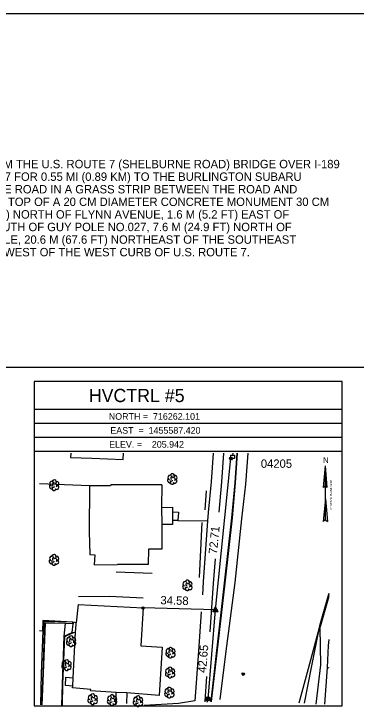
# Model space of a CAD drawing. Extents: x 1454512 to 1455152, y 715836 to 716256.
# Drawn here: x 1454659.9 to 1454782.2, y 716007.5 to 716255.5 of the extents above; entities that cross this region are included whole.
import ezdxf

# ---------------------------------------------------------------- set-up
doc = ezdxf.new("R2010")
doc.units = 0
for name, color, linetype in [('CBP', 7, 'Continuous'), ('CPSM', 7, 'Continuous'), ('Default', 7, 'Continuous'), ('LAHR', 7, 'Continuous'), ('LAPB', 7, 'Continuous'), ('LBC', 7, 'Continuous'), ('LBF', 7, 'Continuous'), ('LFNC', 7, 'Continuous'), ('LSH', 7, 'Continuous'), ('LTD', 7, 'Continuous'), ('LW', 7, 'Continuous'), ('NBL1', 7, 'Continuous'), ('NBL2', 7, 'Continuous'), ('NNA_P', 7, 'Continuous'), ('PET', 7, 'Continuous'), ('PSP', 7, 'Continuous'), ('RC', 7, 'Continuous'), ('RDG', 7, 'Continuous'), ('RDP', 7, 'Continuous'), ('RSW', 7, 'Continuous'), ('U_C', 7, 'Continuous'), ('UEPT', 7, 'Continuous'), ('UGV', 7, 'Continuous')]:
    doc.layers.add(name, color=color, linetype=linetype)

msp = doc.modelspace()

# ---------------------------------------------------------------- linework, layer by layer
at = {"layer": 'CBP'}
for centre, radius in [((1454737.38, 716096.54), 0.469), ((1454737.38, 716096.54), 0.0625), ((1454706, 716043), 0.469), ((1454706, 716043), 0.0625), ((1454729.24, 716010.41), 0.469), ((1454729.24, 716010.41), 0.0625)]:
    msp.add_circle(centre, radius, dxfattribs=at)
at = {"layer": 'CPSM'}
for p, q in [((1454730.98, 716041.74), (1454731.92, 716043.37)), ((1454730.98, 716041.74), (1454731.92, 716042.29)), ((1454730.98, 716041.74), (1454732.86, 716041.74)), ((1454732.86, 716041.74), (1454731.92, 716043.37)), ((1454731.92, 716042.29), (1454731.92, 716043.37)), ((1454731.92, 716042.29), (1454731.92, 716042.29)), ((1454731.92, 716042.29), (1454732.86, 716041.74))]:
    msp.add_line(p, q, dxfattribs=at)
at = {"layer": 'Default'}
for p, q in [((1454731.92, 716042.29), (1454737.38, 716096.54)), ((1454731.92, 716042.29), (1454706, 716043)), ((1454729.24, 716010.41), (1454731.92, 716042.29))]:
    msp.add_line(p, q, dxfattribs=at)
at = {"layer": 'LAHR'}
for points in [[(1454728.58, 716084.91), (1454728.12, 716078.17)], [(1454727.03, 716073.56), (1454726.06, 716053.94)], [(1454709.26, 716055.34), (1454696.46, 716055.8)], [(1454682.91, 716047.17), (1454694.02, 716047.24), (1454706.11, 716046.67)]]:
    msp.add_lwpolyline(points, dxfattribs=at)
at = {"layer": 'LAPB'}
msp.add_lwpolyline([(1454680.96, 716037.97), (1454670.18, 716038.49), (1454670.14, 716034.69), (1454668.99, 716034.8)], dxfattribs=at)
at = {"layer": 'LBC'}
for points in [[(1454712.74, 716087.08), (1454704.74, 716087.07), (1454700.29, 716087.1), (1454694.46, 716087.11), (1454694.35, 716086.71), (1454690.28, 716086.68), (1454686.87, 716086.68), (1454686.73, 716070.41)], [(1454712.74, 716087.08), (1454712.63, 716078.92), (1454712.76, 716072.87), (1454712.7, 716064.08), (1454707.95, 716064.07), (1454707.9, 716058.5), (1454696.94, 716058.58)], [(1454682.85, 716044.21), (1454682.17, 716037.74)], [(1454682.85, 716044.21), (1454706.06, 716043.06), (1454705.24, 716029.42), (1454712.91, 716028.95), (1454711.78, 716011.74), (1454700.28, 716012.6), (1454696.46, 716012.83), (1454687.24, 716013.4), (1454687.42, 716013.81)], [(1454682.15, 716037.12), (1454682.17, 716037.74)]]:
    msp.add_lwpolyline(points, dxfattribs=at)
at = {"layer": 'LBF'}
for points in [[(1454680.22, 716098.33), (1454680.15, 716096.81), (1454687.68, 716096.64), (1454698.86, 716096.14), (1454699.04, 716098.33)], [(1454712.63, 716078.92), (1454716.49, 716079.01), (1454716.51, 716077.43), (1454716.6, 716074.26), (1454716.56, 716072.89), (1454712.76, 716072.87)], [(1454716.51, 716077.43), (1454718.64, 716077.3), (1454718.49, 716074.31), (1454716.6, 716074.26)], [(1454686.73, 716070.41), (1454687.01, 716062.12), (1454688.83, 716061.98), (1454688.61, 716058.49), (1454696.94, 716058.58)], [(1454687.42, 716013.81), (1454680.82, 716014.4), (1454680.87, 716015.04), (1454681.04, 716018.05), (1454681.93, 716034.34), (1454682.15, 716037.12)], [(1454682.17, 716037.74), (1454680.96, 716037.97), (1454681.01, 716037.28)], [(1454680.73, 716034.26), (1454681.93, 716034.34)], [(1454680.87, 716015.04), (1454678.29, 716015.23), (1454678.48, 716018.24), (1454681.04, 716018.05)], [(1454696.32, 716008.65), (1454696.46, 716012.83)], [(1454700.28, 716012.6), (1454700.12, 716008.79)]]:
    msp.add_lwpolyline(points, dxfattribs=at)
at = {"layer": 'LFNC'}
msp.add_lwpolyline([(1454686.87, 716086.68), (1454668.99, 716087.43)], dxfattribs=at)
at = {"layer": 'LSH'}
for p, q in [((1454680.28, 716031.14), (1454680.28, 716031.14)), ((1454680.28, 716031.14), (1454680.28, 716031.14)), ((1454715.8, 716027.07), (1454715.8, 716027.07)), ((1454715.8, 716027.07), (1454715.8, 716027.07)), ((1454678.68, 716022.59), (1454678.68, 716022.59)), ((1454678.68, 716022.59), (1454678.68, 716022.59)), ((1454715.66, 716019.94), (1454715.66, 716019.94)), ((1454715.66, 716019.94), (1454715.66, 716019.94)), ((1454715.41, 716012.76), (1454715.41, 716012.76)), ((1454715.41, 716012.76), (1454715.41, 716012.76)), ((1454694.92, 716010.11), (1454694.92, 716010.11)), ((1454694.92, 716010.11), (1454694.92, 716010.11)), ((1454704.2, 716009.69), (1454704.2, 716009.69)), ((1454704.2, 716009.69), (1454704.2, 716009.69))]:
    msp.add_line(p, q, dxfattribs=at)
for centre in [(1454680.32, 716032.22), (1454715.84, 716028.14), (1454678.71, 716023.67), (1454715.69, 716021.02), (1454715.44, 716013.84), (1454694.95, 716011.18), (1454704.23, 716010.77)]:
    msp.add_arc(centre, 0.785, 335.5272, 180.9563, dxfattribs=at)
for centre, major_axis, ratio, start_param, end_param in [((1454679.69, 716031.64), (0.908, -0.384), 0.895232, 1.570796, 4.712389), ((1454680.12, 716031.49), (-0.156, -0.594), 0.645439, 3.141593, 6.283185), ((1454680.66, 716031.02), (-0.375, 0.5), 0.989748, 3.141593, 6.283185), ((1454681.06, 716031.58), (-0.855, -0.362), 0.949671, 1.570796, 4.712389), ((1454679.47, 716030.61), (0.438, -0.781), 0.959034, 3.141593, 6.283185), ((1454680.28, 716030.02), (0.199, 0.796), 0.942809, 1.570796, 4.712389), ((1454679.94, 716030.58), (-0.469, -0.063), 0.423636, 0, 3.141593), ((1454681.03, 716030.52), (-0.817, 0.594), 0.841452, 1.570796, 4.712389), ((1454714.99, 716026.54), (0.438, -0.781), 0.959034, 3.141593, 6.283185), ((1454715.21, 716027.57), (0.908, -0.384), 0.895232, 1.570796, 4.712389), ((1454715.65, 716027.41), (-0.156, -0.594), 0.645439, 3.141593, 6.283185), ((1454716.18, 716026.94), (-0.375, 0.5), 0.989748, 3.141593, 6.283185), ((1454716.55, 716026.44), (-0.817, 0.594), 0.841452, 1.570796, 4.712389), ((1454716.58, 716027.5), (-0.855, -0.362), 0.949671, 1.570796, 4.712389), ((1454715.8, 716025.94), (0.199, 0.796), 0.942809, 1.570796, 4.712389), ((1454715.46, 716026.5), (-0.469, -0.063), 0.423636, 0, 3.141593), ((1454677.86, 716022.06), (0.438, -0.781), 0.959034, 3.141593, 6.283185), ((1454678.08, 716023.09), (0.908, -0.384), 0.895232, 1.570796, 4.712389), ((1454678.33, 716022.03), (-0.469, -0.063), 0.423636, 0, 3.141593), ((1454678.52, 716022.94), (-0.156, -0.594), 0.645439, 3.141593, 6.283185), ((1454679.05, 716022.47), (-0.375, 0.5), 0.989748, 3.141593, 6.283185), ((1454679.43, 716021.97), (-0.817, 0.594), 0.841452, 1.570796, 4.712389), ((1454679.46, 716023.03), (-0.855, -0.362), 0.949671, 1.570796, 4.712389), ((1454678.68, 716021.47), (0.199, 0.796), 0.942809, 1.570796, 4.712389), ((1454714.85, 716019.41), (0.438, -0.781), 0.959034, 3.141593, 6.283185), ((1454715.06, 716020.44), (0.908, -0.384), 0.895232, 1.570796, 4.712389), ((1454715.32, 716019.38), (-0.469, -0.063), 0.423636, 0, 3.141593), ((1454715.5, 716020.29), (-0.156, -0.594), 0.645439, 3.141593, 6.283185), ((1454716.03, 716019.82), (-0.375, 0.5), 0.989748, 3.141593, 6.283185), ((1454716.41, 716019.32), (-0.817, 0.594), 0.841452, 1.570796, 4.712389), ((1454716.44, 716020.38), (-0.855, -0.362), 0.949671, 1.570796, 4.712389), ((1454715.66, 716018.82), (0.199, 0.796), 0.942809, 1.570796, 4.712389), ((1454714.81, 716013.26), (0.908, -0.384), 0.895232, 1.570796, 4.712389), ((1454714.6, 716012.23), (0.438, -0.781), 0.959034, 3.141593, 6.283185), ((1454715.41, 716011.63), (0.199, 0.796), 0.942809, 1.570796, 4.712389), ((1454715.06, 716012.2), (-0.469, -0.063), 0.423636, 0, 3.141593), ((1454715.25, 716013.1), (-0.156, -0.594), 0.645439, 3.141593, 6.283185), ((1454715.78, 716012.63), (-0.375, 0.5), 0.989748, 3.141593, 6.283185), ((1454716.16, 716012.13), (-0.817, 0.594), 0.841452, 1.570796, 4.712389), ((1454716.19, 716013.2), (-0.855, -0.362), 0.949671, 1.570796, 4.712389), ((1454694.1, 716009.57), (0.438, -0.781), 0.959034, 3.141593, 6.283185), ((1454694.32, 716010.61), (0.908, -0.384), 0.895232, 1.570796, 4.712389), ((1454694.57, 716009.54), (-0.469, -0.063), 0.423636, 0, 3.141593), ((1454694.76, 716010.45), (-0.156, -0.594), 0.645439, 3.141593, 6.283185), ((1454695.29, 716009.98), (-0.375, 0.5), 0.989748, 3.141593, 6.283185), ((1454695.67, 716009.48), (-0.817, 0.594), 0.841452, 1.570796, 4.712389), ((1454695.7, 716010.54), (-0.855, -0.362), 0.949671, 1.570796, 4.712389), ((1454703.38, 716009.16), (0.438, -0.781), 0.959034, 3.141593, 6.283185), ((1454703.6, 716010.19), (0.908, -0.384), 0.895232, 1.570796, 4.712389), ((1454704.04, 716010.04), (-0.156, -0.594), 0.645439, 3.141593, 6.283185), ((1454704.57, 716009.57), (-0.375, 0.5), 0.989748, 3.141593, 6.283185), ((1454704.95, 716009.07), (-0.817, 0.594), 0.841452, 1.570796, 4.712389), ((1454704.98, 716010.13), (-0.855, -0.362), 0.949671, 1.570796, 4.712389), ((1454694.92, 716008.98), (0.199, 0.796), 0.942809, 1.570796, 4.712389), ((1454704.2, 716008.57), (0.199, 0.796), 0.942809, 1.570796, 4.712389), ((1454703.85, 716009.13), (-0.469, -0.063), 0.423636, 0, 3.141593)]:
    msp.add_ellipse(centre, major_axis=major_axis, ratio=ratio, start_param=start_param, end_param=end_param, dxfattribs=at)
at = {"layer": 'LTD'}
for p, q in [((1454716.46, 716089.17), (1454716.46, 716089.17)), ((1454716.46, 716089.17), (1454716.46, 716089.17)), ((1454674.24, 716086.97), (1454674.24, 716086.97)), ((1454674.24, 716086.97), (1454674.24, 716086.97)), ((1454674.18, 716060.23), (1454674.18, 716060.23)), ((1454674.18, 716060.23), (1454674.18, 716060.23)), ((1454721.83, 716051.12), (1454721.83, 716051.12)), ((1454721.83, 716051.12), (1454721.83, 716051.12)), ((1454688, 716010.42), (1454688, 716010.42)), ((1454688, 716010.42), (1454688, 716010.42))]:
    msp.add_line(p, q, dxfattribs=at)
for centre in [(1454674.28, 716088.04), (1454716.5, 716090.25), (1454674.22, 716061.31), (1454721.86, 716052.2), (1454688.03, 716011.5)]:
    msp.add_arc(centre, 0.785, 335.5272, 180.9563, dxfattribs=at)
for centre, major_axis, ratio, start_param, end_param in [((1454715.65, 716088.64), (0.438, -0.781), 0.959034, 3.141593, 6.283185), ((1454715.87, 716089.67), (0.908, -0.384), 0.895232, 1.570796, 4.712389), ((1454716.12, 716088.61), (-0.469, -0.063), 0.423636, 0, 3.141593), ((1454716.3, 716089.52), (-0.156, -0.594), 0.645439, 3.141593, 6.283185), ((1454716.84, 716089.05), (-0.375, 0.5), 0.989748, 3.141593, 6.283185), ((1454717.21, 716088.55), (-0.817, 0.594), 0.841452, 1.570796, 4.712389), ((1454717.24, 716089.61), (-0.855, -0.362), 0.949671, 1.570796, 4.712389), ((1454673.43, 716086.44), (0.438, -0.781), 0.959034, 3.141593, 6.283185), ((1454673.65, 716087.47), (0.908, -0.384), 0.895232, 1.570796, 4.712389), ((1454673.9, 716086.4), (-0.469, -0.063), 0.423636, 0, 3.141593), ((1454674.09, 716087.31), (-0.156, -0.594), 0.645439, 3.141593, 6.283185), ((1454674.62, 716086.84), (-0.375, 0.5), 0.989748, 3.141593, 6.283185), ((1454674.99, 716086.34), (-0.817, 0.594), 0.841452, 1.570796, 4.712389), ((1454675.02, 716087.4), (-0.855, -0.362), 0.949671, 1.570796, 4.712389), ((1454716.46, 716088.05), (0.199, 0.796), 0.942809, 1.570796, 4.712389), ((1454674.24, 716085.84), (0.199, 0.796), 0.942809, 1.570796, 4.712389), ((1454673.59, 716060.73), (0.908, -0.384), 0.895232, 1.570796, 4.712389), ((1454674.96, 716060.67), (-0.855, -0.362), 0.949671, 1.570796, 4.712389), ((1454673.37, 716059.7), (0.438, -0.781), 0.959034, 3.141593, 6.283185), ((1454674.18, 716059.11), (0.199, 0.796), 0.942809, 1.570796, 4.712389), ((1454673.84, 716059.67), (-0.469, -0.063), 0.423636, 0, 3.141593), ((1454674.02, 716060.58), (-0.156, -0.594), 0.645439, 3.141593, 6.283185), ((1454674.56, 716060.11), (-0.375, 0.5), 0.989748, 3.141593, 6.283185), ((1454674.93, 716059.61), (-0.817, 0.594), 0.841452, 1.570796, 4.712389), ((1454721.23, 716051.62), (0.908, -0.384), 0.895232, 1.570796, 4.712389), ((1454721.67, 716051.46), (-0.156, -0.594), 0.645439, 3.141593, 6.283185), ((1454722.2, 716051), (-0.375, 0.5), 0.989748, 3.141593, 6.283185), ((1454722.61, 716051.56), (-0.855, -0.362), 0.949671, 1.570796, 4.712389), ((1454721.02, 716050.59), (0.438, -0.781), 0.959034, 3.141593, 6.283185), ((1454721.83, 716050), (0.199, 0.796), 0.942809, 1.570796, 4.712389), ((1454721.48, 716050.56), (-0.469, -0.063), 0.423636, 0, 3.141593), ((1454722.58, 716050.5), (-0.817, 0.594), 0.841452, 1.570796, 4.712389), ((1454687.4, 716010.92), (0.908, -0.384), 0.895232, 1.570796, 4.712389), ((1454688.78, 716010.86), (-0.855, -0.362), 0.949671, 1.570796, 4.712389), ((1454687.18, 716009.89), (0.438, -0.781), 0.959034, 3.141593, 6.283185), ((1454688, 716009.3), (0.199, 0.796), 0.942809, 1.570796, 4.712389), ((1454687.65, 716009.86), (-0.469, -0.063), 0.423636, 0, 3.141593), ((1454687.84, 716010.76), (-0.156, -0.594), 0.645439, 3.141593, 6.283185), ((1454688.37, 716010.3), (-0.375, 0.5), 0.989748, 3.141593, 6.283185), ((1454688.75, 716009.8), (-0.817, 0.594), 0.841452, 1.570796, 4.712389)]:
    msp.add_ellipse(centre, major_axis=major_axis, ratio=ratio, start_param=start_param, end_param=end_param, dxfattribs=at)
at = {"layer": 'LW'}
for points in [[(1454680.82, 716037.93), (1454670.42, 716038.2), (1454670.17, 716034.78), (1454669.62, 716019.55), (1454669.33, 716008.31)], [(1454680.82, 716037.93), (1454680.9, 716037.38), (1454678.36, 716037.48), (1454670.85, 716037.71), (1454670.18, 716019.7), (1454669.72, 716008.35)], [(1454677.18, 716008.21), (1454677.33, 716015.79), (1454678.02, 716032.79), (1454680.76, 716034.14), (1454680.87, 716033.83)]]:
    msp.add_lwpolyline(points, dxfattribs=at)
at = {"layer": 'NBL1'}
msp.add_lwpolyline([(1454512.16, 715835.51), (1455152.16, 715835.51), (1455152.16, 716255.51), (1454512.16, 716255.51)], close=True, dxfattribs=at)
at = {"layer": 'NBL2'}
for p, q in [((1454512.16, 716129.18), (1455152.16, 716129.18)), ((1454777.16, 716114.01), (1454667.16, 716114.01)), ((1454777.16, 716109.01), (1454667.16, 716109.01)), ((1454777.16, 716104.01), (1454667.16, 716104.01)), ((1454777.16, 716099.01), (1454667.16, 716099.01))]:
    msp.add_line(p, q, dxfattribs=at)
msp.add_lwpolyline([(1454667.16, 716008.01), (1454777.16, 716008.01), (1454777.16, 716124.01), (1454667.16, 716124.01)], close=True, dxfattribs=at)
at = {"layer": 'NNA_P'}
for p, q in [((1454770.46, 716086.1), (1454771.16, 716093.89)), ((1454771.16, 716074.52), (1454771.16, 716093.89)), ((1454771.85, 716086.1), (1454771.16, 716093.89)), ((1454770.46, 716086.1), (1454771.16, 716086.87)), ((1454771.85, 716086.1), (1454771.16, 716086.87)), ((1454771.16, 716082.04), (1454770.44, 716073.88)), ((1454771.16, 716082.04), (1454771.88, 716073.88)), ((1454771.16, 716074.52), (1454770.44, 716073.88)), ((1454771.16, 716074.52), (1454771.88, 716073.88))]:
    msp.add_line(p, q, dxfattribs=at)
at = {"layer": 'PET'}
for points in [[(1454743.48, 716098.33), (1454742.65, 716087.31), (1454741.17, 716074.88), (1454738.8, 716052.13), (1454735.44, 716026.55), (1454733.48, 716010.23)], [(1454772.29, 716047.54), (1454772.57, 716048.26)], [(1454761.84, 716009.07), (1454765.1, 716021.38), (1454769.07, 716035.99)]]:
    msp.add_lwpolyline(points, dxfattribs=at)
at = {"layer": 'PSP'}
for points in [[(1454739.71, 716098.33), (1454738.95, 716087.77), (1454737.85, 716075.21), (1454735.2, 716051.87), (1454732.36, 716026.94), (1454730.51, 716010.64), (1454730.38, 716009.38)], [(1454763.76, 716008.9), (1454766.24, 716021.71), (1454769.07, 716035.99), (1454769.18, 716036.75), (1454772.29, 716047.54)]]:
    msp.add_lwpolyline(points, dxfattribs=at)
at = {"layer": 'RC'}
for points in [[(1454739.52, 716098.33), (1454738.8, 716087.8)], [(1454738.8, 716087.8), (1454737.63, 716075.23), (1454735.01, 716051.83), (1454732.19, 716026.75), (1454730.33, 716010.72), (1454730.03, 716009.39)], [(1454769.07, 716035.99), (1454769.35, 716036.74), (1454772.4, 716047.55)]]:
    msp.add_lwpolyline(points, dxfattribs=at)
at = {"layer": 'RDG'}
msp.add_lwpolyline([(1454676.95, 716008.19), (1454677.2, 716015.78), (1454677.87, 716032.9), (1454678.29, 716037.41), (1454671.05, 716037.53), (1454670.29, 716019.66), (1454669.9, 716008.38)], dxfattribs=at)
at = {"layer": 'RDP'}
msp.add_lwpolyline([(1454772.57, 716021.44), (1454771.94, 716021.67)], dxfattribs=at)
at = {"layer": 'RSW'}
for points in [[(1454731.1, 716098.33), (1454730.31, 716088.16)], [(1454734.77, 716098.33), (1454734, 716088.17)], [(1454730.31, 716088.16), (1454729.3, 716077.15), (1454729.04, 716074.22), (1454727.54, 716052.37), (1454727.27, 716047.73)], [(1454734, 716088.17), (1454733.1, 716077.31)], [(1454718.49, 716074.31), (1454729.04, 716074.22)], [(1454731.8, 716060.58), (1454731.13, 716051.82), (1454729.87, 716034.53)], [(1454767.84, 716008.66), (1454769.6, 716022.73), (1454769.3, 716035.96), (1454769.46, 716036.36), (1454772.57, 716047.23)], [(1454772.57, 716047.51), (1454772.4, 716047.55), (1454772.57, 716048.03)], [(1454726.84, 716041.64), (1454725.82, 716027.52), (1454724.57, 716009.84), (1454718.64, 716008.82), (1454706.47, 716008.14)], [(1454677.87, 716032.9), (1454680.73, 716034.26), (1454681.01, 716037.28), (1454678.29, 716037.41)], [(1454770.94, 716008.58), (1454771.94, 716021.67), (1454772.26, 716029.58), (1454772.57, 716031.76)], [(1454728.72, 716018.45), (1454728.1, 716009.62), (1454728.14, 716009.49)]]:
    msp.add_lwpolyline(points, dxfattribs=at)
at = {"layer": 'UEPT'}
for p, q in [((1454737.4, 716096.47), (1454737.4, 716097.72)), ((1454737.4, 716097.72), (1454738.65, 716097.72)), ((1454738.65, 716096.47), (1454737.4, 716096.47)), ((1454737.84, 716095.84), (1454738.03, 716096.47)), ((1454738.15, 716098.33), (1454738.03, 716097.72)), ((1454738.03, 716097.09), (1454738.03, 716097.09)), ((1454738.65, 716097.72), (1454738.65, 716096.47)), ((1454728.56, 716009.89), (1454728.56, 716011.14)), ((1454728.56, 716011.14), (1454729.81, 716011.14)), ((1454729.81, 716009.89), (1454728.56, 716009.89)), ((1454728.99, 716009.27), (1454729.18, 716009.89)), ((1454729.31, 716011.77), (1454729.18, 716011.14)), ((1454729.18, 716010.52), (1454729.18, 716010.52)), ((1454729.81, 716011.14), (1454729.81, 716009.89))]:
    msp.add_line(p, q, dxfattribs=at)
at = {"layer": 'UGV'}
for radius in [0.469, 0.0625]:
    msp.add_circle((1454741.84, 716019.38), radius, dxfattribs=at)

# ---------------------------------------------------------------- texts
at = {"layer": 'Default'}
for s, p in [('GENERAL LOCATION, BURLINGTON, VT. TO REACH FROM THE U.S. ROUTE 7 (SHELBURNE ROAD) BRIDGE OVER I-189 ', (1454546.94, 716200.29)), ('IN SOUTH BURLINGTON GO NORTH ALONG U.S. ROUTE 7 FOR 0.55 MI (0.89 KM) TO THE BURLINGTON SUBARU ', (1454546.94, 716195.79)), ('DEALERSHIP AND THE MARK ON THE WEST SIDE OF THE ROAD IN A GRASS STRIP BETWEEN THE ROAD AND ', (1454546.94, 716191.29)), ('SIDEWALK. STATION MARK IS A BLANK DISK SET IN THE TOP OF A 20 CM DIAMETER CONCRETE MONUMENT 30 CM ', (1454546.94, 716186.79)), ('BELOW GROUND SURFACE. IT IS ABOUT 122 M (400.3 FT) NORTH OF FLYNN AVENUE, 1.6 M (5.2 FT) EAST OF ', (1454546.94, 716182.29)), ('THE EAST EDGE OF THE SIDEWALK, 30.0 M (98.4 FT) SOUTH OF GUY POLE NO.027, 7.6 M (24.9 FT) NORTH OF ', (1454546.94, 716177.79)), ('A 15 CM APPLE, 11.6 M (38.1 FT) SOUTH OF A 15 CM APPLE, 20.6 M (67.6 FT) NORTHEAST OF THE SOUTHEAST ', (1454546.94, 716173.29)), ('CORNER OF THE SUBARU BUILDING, AND 0.4 M (1.3 FT) WEST OF THE WEST CURB OF U.S. ROUTE 7. ', (1454546.94, 716168.79))]:
    msp.add_text(s, height=3, dxfattribs=at).set_placement(p)
for s, rotation, p in [('72.71', 84.2501, (1454732.41, 716062.16)), ('34.58', 358.431, (1454712.21, 716044.33)), ('42.65', 85.1982, (1454728.52, 716019.71))]:
    msp.add_text(s, height=3, rotation=rotation, dxfattribs=at).set_placement(p)
at = {"layer": 'NBL2'}
for s, height, p in [('     HVCTRL #5     ', 4.75, (1454677.81, 716116.64)), ('NORTH =  716262.101 ', 2.375, (1454693.78, 716110.33)), ('EAST  =  1455587.420', 2.375, (1454694.33, 716105.33)), ('ELEV. =    205.942  ', 2.375, (1454693.89, 716100.33))]:
    msp.add_text(s, height=height, dxfattribs=at).set_placement(p)
at = {"layer": 'NNA_P'}
msp.add_text('N', height=1.97, dxfattribs=at).set_placement((1454770.39, 716094.9))
msp.add_text('VT STATE PLANE GRID', height=0.7, rotation=90.0204, dxfattribs=at).set_placement((1454773.51, 716078.08))
at = {"layer": 'U_C'}
msp.add_text('04205', height=3, dxfattribs=at).set_placement((1454748.11, 716093.14))

doc.saveas('drawing.dxf')
